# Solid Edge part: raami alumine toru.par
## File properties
Title: raami alumine toru
Author: Stella-Marii
Template: Iso Metric Part.par
Last saved by: Stella-Marii
Revision: 22
Application: Solid Edge
Document Number: 34
Density: 7833,000 kg/m^3
Accuracy: 0,990
Username: Stella-Marii
Material: Steel, structural
Face Style: Steel
Fill Style: ANSI32(Steel)
Virtual Style: Brushed steel
Grouping: Metals\Steel
LibraryName: Materials
Coef. of Thermal Exp: 1.3e-05
Thermal Conductivity: 32.0
Specific Heat: 481.0
Modulus of Elasticity: 199947953000.0
Poisson's Ratio: 0.29
Yield Stress: 262000766.0
Ultimate Stress: 358527364.0
Elongation: 0.0
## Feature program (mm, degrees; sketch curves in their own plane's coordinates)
sketch for "unnamed Protrusion 1" plane through (0, 0, 0) normal (1, 0, 0) x-axis (0, 1, 0)
  circle centre (0, 0) radius 22.5
extrude "unnamed Protrusion 1" add finite 500 along -normal
swept protrusion "SweptProtrusion_2"
thinwall "Thinwall_1"  Thickness = 3 mm
sketch for "ExtrudedCutout_1" plane through (124.4012, 0, 359.6163) normal (-0.258819, 0, 0.965926) x-axis (0.965926, 0, 0.258819)
  line (-36.185, -27.5119) -> (-11.1505, -27.5119)
  line (-11.1505, -27.5119) -> (-11.1505, 27.5119)
  line (-11.1505, 27.5119) -> (-36.185, 27.5119)
  line (-36.185, 27.5119) -> (-36.185, -27.5119)
extrude "ExtrudedCutout_1" cut finite 100 along -normal
sketch for "ExtrudedCutout_2" plane through (129.8826, 0, 361.085) normal (-0.258819, 0, 0.965926) x-axis (0, -1, 0)
  line (-12.5, 13.0335) -> (12.5, 13.0335)
  line (12.5, 13.0335) -> (17.1769, 23.2502)
  line (17.1769, 23.2502) -> (-17.1352, 23.2502)
  line (-17.1352, 23.2502) -> (-12.5, 13.0335)
  dimension (linear) = 12.5
extrude "ExtrudedCutout_2" cut finite 255.8397 along -normal
sketch for "ExtrudedCutout_3" plane through (0, 0, 0) normal (0, -1, 0) x-axis (1, 0, 0)
  line (117.1252, 343.6887) -> (141.5986, 364.2243)
  line (141.5986, 364.2243) -> (113.6307, 356.7303)
  line (113.6307, 356.7303) -> (117.1252, 343.6887)
extrude "ExtrudedCutout_3" cut finite 102.9283 symmetric
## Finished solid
Body 1: solid body, 19 faces, 42 edges, 24 vertices.
  Faces by surface: plane 9, cylinder 6, torus 2, offset 1, spline 1
  Edges by curve: line 16, circle 13, intersection 8, ellipse 4, curve on surface 1
Bounding box of the edges (mm; curved faces can reach further): 694.632 x 45.000 x 386.958, from (-500, -22.5, -22.5) to (194.6319, 22.5, 364.4583).
Cylindrical faces by radius (mm): R19.5 x3, R22.5 x3
Toroidal faces (ring radius, tube radius in mm): R73.3685 r19.5 x1, R73.3685 r22.5 x1
Planar faces by outward normal: -x 1, oblique 8
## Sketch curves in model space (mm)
circle centre (0, 0, 0) radius 22.5
line (170.9886, 0, 185.7496) -> (124.4012, 0, 359.6163)
arc centre (112.359, 0, 173.6572) radius 59.8637 from (156.0662, 0, 132.7508) through (169.9822, 0, 157.4328) to (170.9886, 0, 185.7496)
line (53.5673, 0, 23.2339) -> (156.0662, 0, 132.7508)
arc centre (0, 0, 73.3685) radius 73.3685 from (0, 0, 0) through (29.1945, 0, 6.0586) to (53.5673, 0, 23.2339)
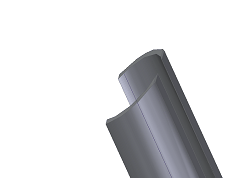
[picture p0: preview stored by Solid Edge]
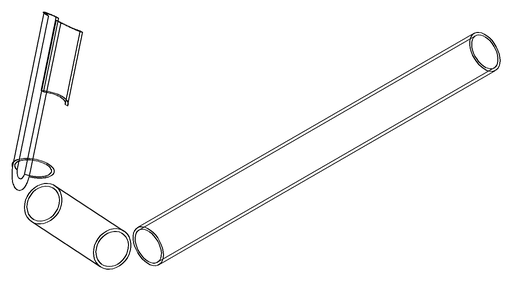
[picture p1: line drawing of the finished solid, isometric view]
